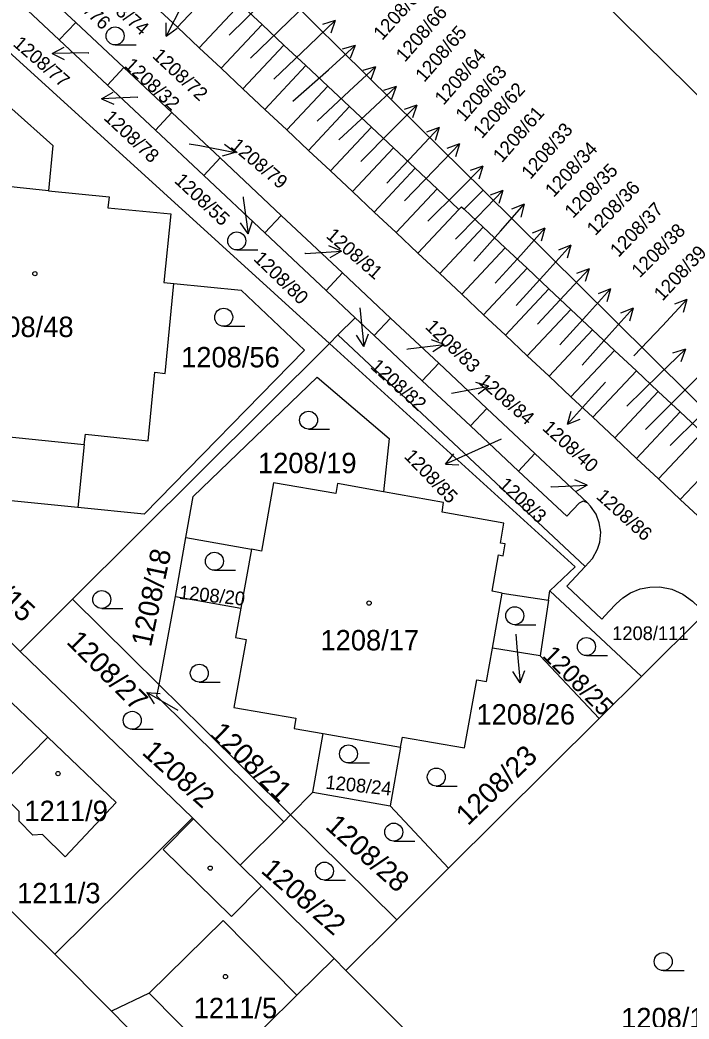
# Model space of a CAD drawing. Extents: x -724107 to -720612, y -1045267 to -1038441.
# Drawn here: x -722035.6 to -721979.8, y -1043824.1 to -1043740.8 of the extents above; entities that cross this region are included whole.
import ezdxf

# ---------------------------------------------------------------- set-up
doc = ezdxf.new("R2010")
doc.units = 0
for name, color, linetype in [('Hranice parcel', 7, 'Continuous'), ('Parcelní čísla', 7, 'Continuous'), ('Pop  PČ popisy', 7, 'Continuous'), ('Vnitřní kresba', 7, 'Continuous'), ('Značky budov', 7, 'Continuous'), ('Značky kultur', 7, 'Continuous')]:
    doc.layers.add(name, color=color, linetype=linetype)

msp = doc.modelspace()

# ---------------------------------------------------------------- linework, layer by layer
at = {"layer": 'Hranice parcel'}
for p, q in [((-721993.47, -1043732.88), (-721971, -1043755.1)), ((-722019.05, -1043737.75), (-722022.47, -1043741.39)), ((-722032.31, -1043742.44), (-722035.37, -1043739.57)), ((-722022.47, -1043741.39), (-722024.3, -1043739.68)), ((-722017.23, -1043739.46), (-722020.65, -1043743.1)), ((-722017.23, -1043739.46), (-722015.41, -1043741.17)), ((-722032.31, -1043742.44), (-722030.94, -1043740.99)), ((-722030.94, -1043740.99), (-722026.93, -1043744.75)), ((-722020.65, -1043743.1), (-722022.47, -1043741.39)), ((-722015.41, -1043741.17), (-722018.83, -1043744.81)), ((-722015.41, -1043741.17), (-722013.59, -1043742.88)), ((-722009.8, -1043767.74), (-722037.95, -1043742.15)), ((-722028.3, -1043746.21), (-722032.31, -1043742.44)), ((-722018.83, -1043744.81), (-722020.65, -1043743.1)), ((-722013.59, -1043742.88), (-722017.01, -1043746.53)), ((-722013.59, -1043742.88), (-722011.76, -1043744.59)), ((-722028.3, -1043746.21), (-722026.93, -1043744.75)), ((-722026.93, -1043744.75), (-722022.93, -1043748.51)), ((-722017.01, -1043746.53), (-722018.83, -1043744.81)), ((-722011.76, -1043744.59), (-722015.18, -1043748.24)), ((-722011.76, -1043744.59), (-722009.94, -1043746.3)), ((-722024.29, -1043749.97), (-722028.3, -1043746.21)), ((-722015.18, -1043748.24), (-722017.01, -1043746.53)), ((-722009.94, -1043746.3), (-722013.36, -1043749.95)), ((-722009.94, -1043746.3), (-722008.12, -1043748.01)), ((-722013.36, -1043749.95), (-722015.18, -1043748.24)), ((-722008.12, -1043748.01), (-722011.54, -1043751.66)), ((-722008.12, -1043748.01), (-722006.29, -1043749.73)), ((-722024.29, -1043749.97), (-722022.93, -1043748.51)), ((-722022.93, -1043748.51), (-722018.92, -1043752.28)), ((-722020.28, -1043753.74), (-722024.29, -1043749.97)), ((-722011.54, -1043751.66), (-722013.36, -1043749.95)), ((-722006.29, -1043749.73), (-722009.71, -1043753.37)), ((-722006.29, -1043749.73), (-722004.47, -1043751.44)), ((-722009.71, -1043753.37), (-722011.54, -1043751.66)), ((-722004.47, -1043751.44), (-722007.89, -1043755.08)), ((-722004.47, -1043751.44), (-722002.65, -1043753.15)), ((-722020.28, -1043753.74), (-722018.92, -1043752.28)), ((-722018.92, -1043752.28), (-722013.82, -1043757.07)), ((-722002.65, -1043753.15), (-722006.07, -1043756.79)), ((-722002.65, -1043753.15), (-722000.83, -1043754.86)), ((-722015.18, -1043758.53), (-722020.28, -1043753.74)), ((-722007.89, -1043755.08), (-722009.71, -1043753.37)), ((-722000.83, -1043754.86), (-722004.25, -1043758.51)), ((-722000.83, -1043754.86), (-721999.01, -1043756.57)), ((-721998.58, -1043756.56), (-721996.99, -1043754.98)), ((-722006.07, -1043756.79), (-722007.89, -1043755.08)), ((-721999.01, -1043756.57), (-722002.43, -1043760.21)), ((-721998.58, -1043756.56), (-721996.98, -1043758.06)), ((-722015.18, -1043758.53), (-722013.82, -1043757.07)), ((-722013.82, -1043757.07), (-722008.72, -1043761.86)), ((-722004.25, -1043758.51), (-722006.07, -1043756.79)), ((-722000.61, -1043761.92), (-721996.98, -1043758.06)), ((-721996.98, -1043758.06), (-721995.16, -1043759.77)), ((-722010.08, -1043763.32), (-722015.18, -1043758.53)), ((-722002.43, -1043760.21), (-722004.25, -1043758.51)), ((-721998.78, -1043763.64), (-721995.16, -1043759.77)), ((-721995.16, -1043759.77), (-721993.33, -1043761.48)), ((-722000.61, -1043761.92), (-722002.43, -1043760.21)), ((-721996.96, -1043765.35), (-721993.33, -1043761.48)), ((-721993.33, -1043761.48), (-721991.51, -1043763.19)), ((-722010.08, -1043763.32), (-722008.72, -1043761.86)), ((-721998.78, -1043763.64), (-722000.61, -1043761.92)), ((-722007.65, -1043765.6), (-722010.08, -1043763.32)), ((-721995.14, -1043767.06), (-721991.51, -1043763.19)), ((-721991.51, -1043763.19), (-721989.69, -1043764.91)), ((-721996.96, -1043765.35), (-721998.78, -1043763.64)), ((-721993.32, -1043768.77), (-721989.69, -1043764.91)), ((-721989.69, -1043764.91), (-721987.87, -1043766.62)), ((-722007.65, -1043765.6), (-722009.1, -1043767.04)), ((-722006.07, -1043767.08), (-722007.65, -1043765.6)), ((-722006.07, -1043767.08), (-722004.7, -1043765.63)), ((-722004.7, -1043765.63), (-722000.69, -1043769.4)), ((-721995.14, -1043767.06), (-721996.96, -1043765.35)), ((-721991.49, -1043770.48), (-721987.87, -1043766.62)), ((-721987.87, -1043766.62), (-721986.04, -1043768.33)), ((-722009.8, -1043767.74), (-722009.1, -1043767.04)), ((-722009.1, -1043767.04), (-721988.48, -1043786.34)), ((-722002.06, -1043770.85), (-722006.07, -1043767.08)), ((-721993.32, -1043768.77), (-721995.14, -1043767.06)), ((-722031.2, -1043789.07), (-722009.8, -1043767.74)), ((-721991.49, -1043770.48), (-721993.32, -1043768.77)), ((-721989.67, -1043772.19), (-721986.04, -1043768.33)), ((-721986.04, -1043768.33), (-721984.22, -1043770.04)), ((-722002.06, -1043770.85), (-722000.69, -1043769.4)), ((-722000.69, -1043769.4), (-721996.68, -1043773.16)), ((-721989.67, -1043772.19), (-721991.49, -1043770.48)), ((-721987.85, -1043773.9), (-721984.22, -1043770.04)), ((-721984.22, -1043770.04), (-721982.4, -1043771.75)), ((-721998.05, -1043774.61), (-722002.06, -1043770.85)), ((-721987.85, -1043773.9), (-721989.67, -1043772.19)), ((-721986.03, -1043775.61), (-721982.4, -1043771.75)), ((-721982.4, -1043771.75), (-721980.57, -1043773.46)), ((-721998.05, -1043774.61), (-721996.68, -1043773.16)), ((-721996.68, -1043773.16), (-721992.67, -1043776.92)), ((-721986.03, -1043775.61), (-721987.85, -1043773.9)), ((-721984.2, -1043777.33), (-721980.57, -1043773.46)), ((-721980.57, -1043773.46), (-721978.75, -1043775.17)), ((-721994.04, -1043778.38), (-721998.05, -1043774.61)), ((-721984.2, -1043777.33), (-721986.03, -1043775.61)), ((-721982.38, -1043779.04), (-721978.75, -1043775.17)), ((-722030.23, -1043776.18), (-722030.78, -1043781.42)), ((-721994.04, -1043778.38), (-721992.67, -1043776.92)), ((-721992.67, -1043776.92), (-721988.3, -1043781.03)), ((-721982.38, -1043779.04), (-721984.2, -1043777.33)), ((-721980.56, -1043780.75), (-721976.93, -1043776.88)), ((-721980.56, -1043780.75), (-721982.38, -1043779.04)), ((-722030.78, -1043781.42), (-722049.31, -1043779.56)), ((-721978.74, -1043782.46), (-721980.56, -1043780.75)), ((-722022.64, -1043788.83), (-722021.78, -1043783.93)), ((-722021.78, -1043783.93), (-722016.3, -1043784.9)), ((-722016.3, -1043784.9), (-722017.18, -1043789.8)), ((-722031.2, -1043789.07), (-722035.57, -1043793.43)), ((-722024, -1043796.19), (-722031.2, -1043789.07)), ((-722024, -1043796.19), (-722022.64, -1043788.83)), ((-722022.64, -1043788.83), (-722017.18, -1043789.8)), ((-721996.21, -1043793.14), (-721995.41, -1043788.55)), ((-721995.41, -1043788.55), (-721991.55, -1043789.14)), ((-721991.55, -1043789.14), (-721992.25, -1043793.78)), ((-721991.55, -1043789.14), (-721991.43, -1043788.38)), ((-721983.79, -1043795.5), (-721991.43, -1043788.38)), ((-721978.49, -1043790.23), (-721983.79, -1043795.5)), ((-722035.57, -1043793.43), (-722037.54, -1043791.53)), ((-721992.25, -1043793.78), (-721996.21, -1043793.14)), ((-722035.57, -1043793.43), (-722021.22, -1043807.29)), ((-721987.33, -1043799.02), (-721992.25, -1043793.78)), ((-721983.79, -1043795.5), (-721987.33, -1043799.02)), ((-721987.33, -1043799.02), (-721999.87, -1043811.49)), ((-722011.18, -1043805.15), (-722010.31, -1043800.27)), ((-722010.31, -1043800.27), (-722003.87, -1043801.41)), ((-722003.87, -1043801.41), (-722004.74, -1043806.3)), ((-722048.38, -1043803.18), (-722032.69, -1043818.66)), ((-722013.05, -1043807.03), (-722011.18, -1043805.15)), ((-722011.18, -1043805.15), (-722004.74, -1043806.3)), ((-722004.74, -1043806.3), (-721999.87, -1043811.49)), ((-722032.69, -1043818.66), (-722021.22, -1043807.29)), ((-722013.05, -1043807.03), (-722013.6, -1043807.62)), ((-722004.19, -1043815.79), (-722013.05, -1043807.03)), ((-722017.23, -1043811.24), (-722013.6, -1043807.62)), ((-721999.87, -1043811.49), (-722004.19, -1043815.79)), ((-722004.19, -1043815.79), (-722008.44, -1043820.02)), ((-722032.69, -1043818.66), (-722027.97, -1043823.4)), ((-722008.44, -1043820.02), (-722009.4, -1043819.01)), ((-722008.44, -1043820.02), (-721998.74, -1043829.68)), ((-722027.97, -1043823.4), (-722010.4, -1043841.17))]:
    msp.add_line(p, q, dxfattribs=at)
for points in [[(-722017.56, -1043734.62), (-722002.37, -1043749.65), (-721996.99, -1043754.98)], [(-722034.95, -1043737.22), (-722033.95, -1043738.16), (-722030.94, -1043740.99)], [(-722051.77, -1043759.8), (-722051.49, -1043757.09), (-722039.7, -1043745.13), (-722032.84, -1043751.26), (-722033.22, -1043755.02)], [(-722033.22, -1043755.02), (-722037.12, -1043754.62), (-722037.18, -1043755.48), (-722042.41, -1043754.94), (-722043.01, -1043760.66), (-722043.88, -1043760.58)], [(-721996.99, -1043754.98), (-721986.16, -1043765.7), (-721969.96, -1043781.75)], [(-722033.22, -1043755.02), (-722028.15, -1043755.53), (-722028.27, -1043756.43), (-722023.01, -1043756.94), (-722023.61, -1043762.67), (-722022.76, -1043762.76)], [(-721999.01, -1043756.57), (-721998.8, -1043756.35), (-721998.58, -1043756.56)], [(-722008.72, -1043761.86), (-722006.24, -1043764.19), (-722004.7, -1043765.63)], [(-722022.76, -1043762.76), (-722017.15, -1043763.3), (-722011.88, -1043768.3), (-722025.25, -1043781.97), (-722030.78, -1043781.42)], [(-722030.23, -1043776.18), (-722030.14, -1043775.3), (-722024.91, -1043775.86), (-722024.36, -1043770.14), (-722023.49, -1043770.25), (-722022.76, -1043762.76)], [(-721991.43, -1043788.38), (-721989.33, -1043786.37), (-722009.8, -1043767.74)], [(-722043.85, -1043769.25), (-722044.32, -1043773.87), (-722039.12, -1043774.42), (-722039.2, -1043775.25), (-722030.23, -1043776.18)], [(-722021.78, -1043783.93), (-722021.17, -1043780.5), (-722010.82, -1043770.56), (-722004.81, -1043775.67), (-722005.29, -1043780.11)], [(-721988.3, -1043781.03), (-721988.66, -1043780.89), (-721989, -1043781.05), (-721990.03, -1043782.15), (-721994.04, -1043778.38)], [(-722005.29, -1043780.11), (-722009.13, -1043779.43), (-722009.28, -1043780.26), (-722014.46, -1043779.37), (-722015.46, -1043785.05), (-722016.3, -1043784.9)], [(-721995.41, -1043788.55), (-721996.24, -1043788.39), (-721995.71, -1043785.37), (-721995.33, -1043785.44), (-721995.16, -1043784.46), (-721995.55, -1043784.39), (-721995.27, -1043782.74), (-722000.41, -1043781.82), (-722000.29, -1043780.99), (-722005.29, -1043780.11)], [(-721988.48, -1043786.34), (-721987.89, -1043785.67), (-721987.45, -1043784.9), (-721987.27, -1043784.3), (-721987.19, -1043783.47), (-721987.31, -1043782.69), (-721987.58, -1043781.97), (-721988.04, -1043781.3), (-721988.3, -1043781.03)], [(-721988.48, -1043786.34), (-721990.02, -1043787.98), (-721987.11, -1043790.72), (-721986.52, -1043790.09), (-721985.91, -1043789.44), (-721985.36, -1043788.95), (-721984.72, -1043788.54), (-721983.9, -1043788.2), (-721983.11, -1043788.05), (-721982.28, -1043788.03), (-721981.26, -1043788.23), (-721980.35, -1043788.64), (-721979.55, -1043789.24), (-721978.49, -1043790.23)], [(-722017.18, -1043789.8), (-722017.62, -1043792.25), (-722016.73, -1043792.41), (-722017.77, -1043798.09), (-722012.59, -1043798.99), (-722012.74, -1043799.84), (-722010.31, -1043800.27)], [(-722003.87, -1043801.41), (-722003.71, -1043800.56), (-721998.55, -1043801.46), (-721997.52, -1043795.78), (-721996.7, -1043795.93), (-721996.21, -1043793.14)], [(-722035.65, -1043807.57), (-722035.65, -1043806.76), (-722037.27, -1043805.15), (-722038.5, -1043806.44), (-722042.84, -1043802.3), (-722037.48, -1043796.57), (-722033.28, -1043800.56), (-722027.56, -1043806), (-722031.81, -1043810.53), (-722033.72, -1043808.67), (-722034.51, -1043808.72), (-722035.65, -1043807.57)], [(-722013.6, -1043807.62), (-722024.18, -1043797.15), (-722024, -1043796.19)], [(-722024, -1043796.19), (-722020.39, -1043799.76), (-722013.05, -1043807.03)], [(-722021.22, -1043807.29), (-722021.13, -1043807.37), (-722017.23, -1043811.24)], [(-722009.4, -1043819.01), (-722015.47, -1043812.99), (-722017.23, -1043811.24)], [(-722009.4, -1043819.01), (-722012.52, -1043822.08), (-722017.8, -1043827.3), (-722018.66, -1043828.14), (-722020.08, -1043826.7), (-722024.82, -1043821.89), (-722027.97, -1043823.4)]]:
    msp.add_lwpolyline(points, dxfattribs=at)
at = {"layer": 'Pop  PČ popisy'}
for p, q in [((-722013.21, -1043740.9), (-722011.051, -1043738.815)), ((-722022.04, -1043739.47), (-722023.402, -1043742.144)), ((-722018.17, -1043742.05), (-722015.41, -1043739.35)), ((-722011.48, -1043742.91), (-722009.321, -1043740.825)), ((-722009.321, -1043740.825), (-722010.39, -1043741.161)), ((-722009.321, -1043740.825), (-722009.694, -1043741.881)), ((-722023.402, -1043742.144), (-722023.394, -1043741.024)), ((-722023.402, -1043742.144), (-722022.502, -1043741.479)), ((-722016.38, -1043743.96), (-722013.21, -1043740.9)), ((-722032.911, -1043743.582), (-722031.918, -1043743.064)), ((-722014.44, -1043745.73), (-722011.48, -1043742.91)), ((-722009.89, -1043744.93), (-722007.66, -1043742.922)), ((-722007.66, -1043742.922), (-722008.739, -1043743.22)), ((-722007.66, -1043742.922), (-722008.069, -1043743.964)), ((-722029.91, -1043743.53), (-722032.911, -1043743.582)), ((-722032.911, -1043743.582), (-722031.9, -1043744.066)), ((-722029.91, -1043743.53), (-722029.86, -1043743.53)), ((-722012.85, -1043747.55), (-722009.89, -1043744.93)), ((-722008.15, -1043746.73), (-722005.955, -1043744.683)), ((-722005.955, -1043744.683), (-722007.029, -1043745)), ((-722005.955, -1043744.683), (-722006.346, -1043745.733)), ((-722006.43, -1043748.39), (-722004.235, -1043746.343)), ((-722004.235, -1043746.343), (-722005.309, -1043746.66)), ((-722004.235, -1043746.343), (-722004.626, -1043747.393)), ((-722028.787, -1043747.367), (-722027.813, -1043746.815)), ((-722025.79, -1043747.21), (-722028.787, -1043747.367)), ((-722028.787, -1043747.367), (-722027.761, -1043747.815)), ((-722025.79, -1043747.21), (-722025.77, -1043747.21)), ((-722010.81, -1043749.23), (-722008.15, -1043746.73)), ((-722004.64, -1043750.01), (-722002.518, -1043747.888)), ((-722002.518, -1043747.888), (-722003.58, -1043748.242)), ((-722002.518, -1043747.888), (-722002.872, -1043748.95)), ((-722009.02, -1043750.78), (-722006.43, -1043748.39)), ((-722002.71, -1043751.94), (-722000.663, -1043749.745)), ((-722000.663, -1043749.745), (-722001.713, -1043750.136)), ((-722000.663, -1043749.745), (-722000.98, -1043750.819)), ((-722007.19, -1043752.57), (-722004.64, -1043750.01)), ((-722021.49, -1043751.1), (-722020.61, -1043751.26)), ((-722020.61, -1043751.26), (-722017.664, -1043751.833)), ((-722017.664, -1043751.833), (-722018.552, -1043751.15)), ((-722001.05, -1043753.28), (-721998.965, -1043751.121)), ((-721998.965, -1043751.121), (-722000.021, -1043751.494)), ((-721998.965, -1043751.121), (-721999.301, -1043752.19)), ((-722017.664, -1043751.833), (-722018.743, -1043752.133)), ((-722005.01, -1043754.38), (-722002.71, -1043751.94)), ((-722003.54, -1043755.86), (-722001.05, -1043753.28)), ((-721999.13, -1043755.1), (-721997.008, -1043752.978)), ((-721997.008, -1043752.978), (-721998.07, -1043753.332)), ((-721997.008, -1043752.978), (-721997.362, -1043754.04)), ((-721997.44, -1043757.16), (-721995.355, -1043755.001)), ((-721995.355, -1043755.001), (-721996.411, -1043755.374)), ((-721995.355, -1043755.001), (-721995.691, -1043756.07)), ((-722017, -1043755.52), (-722016.99, -1043755.63)), ((-722016.99, -1043755.63), (-722016.572, -1043758.602)), ((-722001.59, -1043757.56), (-721999.13, -1043755.1)), ((-721995.55, -1043758.39), (-721993.581, -1043756.125)), ((-721993.581, -1043756.125), (-721994.616, -1043756.552)), ((-721993.581, -1043756.125), (-721993.86, -1043757.209)), ((-721999.3, -1043759.05), (-721997.44, -1043757.16)), ((-722016.572, -1043758.602), (-722017.208, -1043757.68)), ((-722016.572, -1043758.602), (-722016.216, -1043757.54)), ((-721993.86, -1043760.38), (-721991.852, -1043758.15)), ((-721991.852, -1043758.15), (-721992.894, -1043758.559)), ((-721991.852, -1043758.15), (-721992.15, -1043759.229)), ((-721997.76, -1043760.9), (-721995.55, -1043758.39)), ((-722008.806, -1043760.041), (-722009.84, -1043759.611)), ((-721991.69, -1043761.79), (-721989.682, -1043759.56)), ((-721989.682, -1043759.56), (-721990.724, -1043759.969)), ((-721989.682, -1043759.56), (-721989.98, -1043760.639)), ((-722011.8, -1043760.25), (-722011.86, -1043760.25)), ((-722011.8, -1043760.25), (-722008.806, -1043760.041)), ((-722008.806, -1043760.041), (-722009.77, -1043760.61)), ((-721995.99, -1043762.72), (-721993.86, -1043760.38)), ((-721990.21, -1043763.71), (-721988.163, -1043761.515)), ((-721988.163, -1043761.515), (-721989.213, -1043761.906)), ((-721988.163, -1043761.515), (-721988.48, -1043762.589)), ((-721994.23, -1043764.58), (-721991.69, -1043761.79)), ((-721988.38, -1043765.43), (-721986.372, -1043763.2)), ((-721986.372, -1043763.2), (-721987.414, -1043763.609)), ((-721986.372, -1043763.2), (-721986.67, -1043764.279)), ((-721992.45, -1043766.14), (-721990.21, -1043763.71)), ((-721982.05, -1043766.29), (-721980.003, -1043764.095)), ((-721980.003, -1043764.095), (-721981.053, -1043764.486)), ((-721980.003, -1043764.095), (-721980.32, -1043765.169)), ((-722007.28, -1043764.77), (-722007.25, -1043765.02)), ((-721986.5, -1043767.03), (-721984.492, -1043764.8)), ((-721984.492, -1043764.8), (-721985.534, -1043765.209)), ((-721984.492, -1043764.8), (-721984.79, -1043765.879)), ((-722007.25, -1043765.02), (-722006.936, -1043768.005)), ((-721990.6, -1043767.86), (-721988.38, -1043765.43)), ((-721984.43, -1043768.79), (-721982.05, -1043766.29)), ((-722006.936, -1043768.005), (-722007.539, -1043767.061)), ((-722006.936, -1043768.005), (-722006.543, -1043766.956)), ((-722000.251, -1043767.834), (-722001.306, -1043767.459)), ((-721988.74, -1043769.55), (-721986.5, -1043767.03)), ((-722003.36, -1043768.21), (-722003.23, -1043768.2)), ((-722003.23, -1043768.2), (-722000.251, -1043767.834)), ((-722000.251, -1043767.834), (-722001.184, -1043768.453)), ((-721982.3, -1043770.31), (-721980.141, -1043768.225)), ((-721980.141, -1043768.225), (-721981.21, -1043768.561)), ((-721980.141, -1043768.225), (-721980.514, -1043769.281)), ((-721985.03, -1043772.98), (-721982.3, -1043770.31)), ((-721980.74, -1043772.2), (-721978.618, -1043770.078)), ((-721999.47, -1043771.87), (-721996.524, -1043771.297)), ((-721996.524, -1043771.297), (-721997.603, -1043770.997)), ((-721996.524, -1043771.297), (-721997.412, -1043771.98)), ((-721986.8, -1043770.96), (-721987.95, -1043772.24)), ((-721999.63, -1043771.9), (-721999.47, -1043771.87)), ((-721987.95, -1043772.24), (-721989.958, -1043774.47)), ((-721983.46, -1043774.92), (-721980.74, -1043772.2)), ((-721989.958, -1043774.47), (-721989.66, -1043773.391)), ((-721989.958, -1043774.47), (-721988.916, -1043774.061)), ((-721981.4, -1043776.25), (-721979, -1043773.85)), ((-721995.5, -1043775.72), (-721997.4, -1043776.58)), ((-721997.4, -1043776.58), (-722000.142, -1043777.801)), ((-722000.142, -1043777.801), (-721999.43, -1043776.936)), ((-722000.142, -1043777.801), (-721999.023, -1043777.851)), ((-721988.333, -1043779.553), (-721989.359, -1043779.105)), ((-721991.33, -1043779.71), (-721991.34, -1043779.71)), ((-721991.33, -1043779.71), (-721988.333, -1043779.553)), ((-721988.333, -1043779.553), (-721989.307, -1043780.105)), ((-721994.28, -1043791.97), (-721994.18, -1043793.05)), ((-721994.18, -1043793.05), (-721993.918, -1043796.04)), ((-721993.918, -1043796.04), (-721994.505, -1043795.086)), ((-721993.918, -1043796.04), (-721993.507, -1043794.998)), ((-722022.42, -1043798.35), (-722025.019, -1043796.85)), ((-722025.019, -1043796.85), (-722023.901, -1043796.917)), ((-722025.019, -1043796.85), (-722024.402, -1043797.784))]:
    msp.add_line(p, q, dxfattribs=at)
at = {"layer": 'Vnitřní kresba'}
for p, q in [((-722021.13, -1043807.37), (-722023.66, -1043809.92)), ((-722017.96, -1043815.5), (-722023.66, -1043809.92)), ((-722015.47, -1043812.99), (-722017.96, -1043815.5)), ((-722024.82, -1043821.89), (-722018.67, -1043815.85)), ((-722018.67, -1043815.85), (-722012.52, -1043822.08))]:
    msp.add_line(p, q, dxfattribs=at)
msp.add_lwpolyline([(-722037.27, -1043805.15), (-722037.53, -1043804.88), (-722033.28, -1043800.56)], dxfattribs=at)
at = {"layer": 'Značky budov'}
for centre in [(-722034.347, -1043761.929), (-722006.497, -1043789.389), (-722032.417, -1043803.599), (-722019.737, -1043811.479), (-722018.467, -1043820.519)]:
    msp.add_circle(centre, 0.175, dxfattribs=at)
at = {"layer": 'Značky kultur'}
for p, q in [((-722027.663, -1043742.86), (-722025.913, -1043742.86)), ((-722017.523, -1043759.95), (-722015.773, -1043759.95)), ((-722018.613, -1043766.31), (-722016.863, -1043766.31)), ((-722011.543, -1043774.89), (-722009.793, -1043774.89)), ((-722019.383, -1043786.65), (-722017.633, -1043786.65)), ((-722028.773, -1043789.84), (-722027.023, -1043789.84)), ((-721994.353, -1043791.19), (-721992.603, -1043791.19)), ((-721988.383, -1043793.76), (-721986.633, -1043793.76)), ((-722020.643, -1043795.98), (-722018.893, -1043795.98)), ((-722026.233, -1043799.91), (-722024.483, -1043799.91)), ((-722008.213, -1043802.71), (-722006.463, -1043802.71)), ((-722000.893, -1043804.64), (-721999.143, -1043804.64)), ((-722004.443, -1043809.23), (-722002.693, -1043809.23)), ((-722010.213, -1043812.48), (-722008.463, -1043812.48)), ((-721981.983, -1043820.02), (-721980.233, -1043820.02))]:
    msp.add_line(p, q, dxfattribs=at)
for centre in [(-722027.663, -1043742.11), (-722017.523, -1043759.2), (-722018.613, -1043765.56), (-722011.543, -1043774.14), (-722019.383, -1043785.9), (-722028.773, -1043789.09), (-721994.353, -1043790.44), (-721988.383, -1043793.01), (-722020.643, -1043795.23), (-722026.233, -1043799.16), (-722008.213, -1043801.96), (-722000.893, -1043803.89), (-722004.443, -1043808.48), (-722010.213, -1043811.73), (-721981.983, -1043819.27)]:
    msp.add_circle(centre, 0.75, dxfattribs=at)

# ---------------------------------------------------------------- texts
at = {"layer": 'Parcelní čísla'}
for s, height, rotation, p in [('1208/76', 1.139, 316, (-722032.685, -1043737.853)), ('1208/74', 1.139, 319, (-722029.624, -1043738.532)), ('1208/67', 1.139, 48, (-722005.407, -1043742.542)), ('1208/66', 1.139, 49, (-722003.517, -1043744.364)), ('1208/65', 1.139, 49, (-722001.897, -1043746.034)), ('1208/77', 1.139, 319, (-722036.234, -1043742.882)), ('1208/72', 1.139, 317, (-722024.629, -1043743.862)), ('1208/64', 1.139, 49, (-722000.287, -1043747.944)), ('1208/32', 1.139, 317, (-722026.958, -1043744.656)), ('1208/63', 1.139, 49, (-721998.547, -1043749.324)), ('1208/62', 1.139, 48, (-721997.097, -1043750.732)), ('1208/61', 1.139, 49, (-721995.427, -1043752.744)), ('1208/78', 1.139, 317, (-722028.679, -1043749.022)), ('1208/33', 1.139, 49, (-721993.057, -1043754.134)), ('1208/79', 1.139, 320, (-722018.115, -1043751.403)), ('1208/34', 1.139, 47, (-721991.117, -1043755.629)), ('1208/35', 1.139, 46, (-721989.506, -1043757.375)), ('1208/55', 1.139, 317, (-722022.789, -1043754.272)), ('1208/36', 1.139, 46, (-721987.656, -1043758.825)), ('1208/37', 1.139, 46, (-721985.716, -1043760.625)), ('1208/81', 1.139, 319, (-722010.154, -1043758.872)), ('1208/38', 1.139, 45, (-721983.945, -1043762.331)), ('1208/39', 1.139, 47, (-721982.047, -1043764.269)), ('1208/80', 1.139, 316, (-722016.195, -1043760.763)), ('1208/83', 1.139, 316, (-722001.885, -1043766.443)), ('1208/82', 1.139, 318, (-722006.462, -1043769.762)), ('1208/84', 1.139, 319, (-721997.504, -1043771.002)), ('1208/40', 1.139, 318, (-721992.132, -1043774.892)), ('1208/85', 1.139, 314, (-722003.645, -1043777.215)), ('1208/3', 1.139, 317, (-721995.778, -1043779.626)), ('1208/86', 1.139, 318, (-721987.642, -1043780.602)), ('1208/15', 1.7, 317, (-722041.339, -1043785.481)), ('1208/18', 1.7, 78, (-722024.676, -1043793.11)), ('1208/20', 1.139, 354, (-722022.376, -1043789.027)), ('1208/27', 1.7, 315, (-722031.794, -1043792.697)), ('1208/25', 1.484, 315, (-721992.123, -1043793.835)), ('1208/21', 1.7, 316, (-722019.851, -1043800.365)), ('1208/2', 1.7, 318, (-722025.508, -1043801.931)), ('1208/23', 1.7, 44, (-721998.26, -1043808.007)), ('1208/24', 1.139, 354, (-722010.166, -1043804.857)), ('1208/28', 1.7, 318, (-722010.231, -1043808.103)), ('1208/22', 1.7, 319, (-722015.594, -1043811.793))]:
    msp.add_text(s, height=height, rotation=rotation, dxfattribs=at).set_placement(p)
for s, height, p in [('1208/48', 1.7, (-722039.34, -1043767.21)), ('1208/56', 1.7, (-722022.158, -1043769.74)), ('1208/19', 1.7, (-722015.758, -1043778.56)), ('1208/17', 1.7, (-722010.548, -1043793.33)), ('1208/111', 1.139, (-721986.238, -1043792.469)), ('1208/26', 1.7, (-721997.548, -1043799.51)), ('1211/9', 1.7, (-722035.22, -1043807.56)), ('1211/3', 1.7, (-722035.83, -1043814.41)), ('1211/5', 1.7, (-722021.11, -1043823.99)), ('1208/1', 1.7, (-721985.49, -1043824.83))]:
    msp.add_text(s, height=height, dxfattribs=at).set_placement(p)

doc.saveas('drawing.dxf')
